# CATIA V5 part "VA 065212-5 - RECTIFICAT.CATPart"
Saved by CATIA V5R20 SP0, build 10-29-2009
Part number: VA 065212-5 - RECTIFICAT
Revision: ANY
Definition: UNKNOWN
Nomenclature: VA 065212-5 - RECTIFICAT
Source: Unknown
Bounding box of the stored display mesh (mm): x -2.5 to 2.5, y 0.2 to 1.6, z -2.5 to 2.5
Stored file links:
  C:\Users\Utente\Desktop\IO LAVORO\3D X SITO CF\CUMSA\3D files VA\VA 065212\VA 065212-5 - RECTIFICAT.CATPart
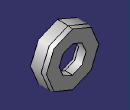
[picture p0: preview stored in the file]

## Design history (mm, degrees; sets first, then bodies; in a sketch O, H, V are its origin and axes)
Body1 "Cortar-Extruir1" (main body)
  Solid1: solid without history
